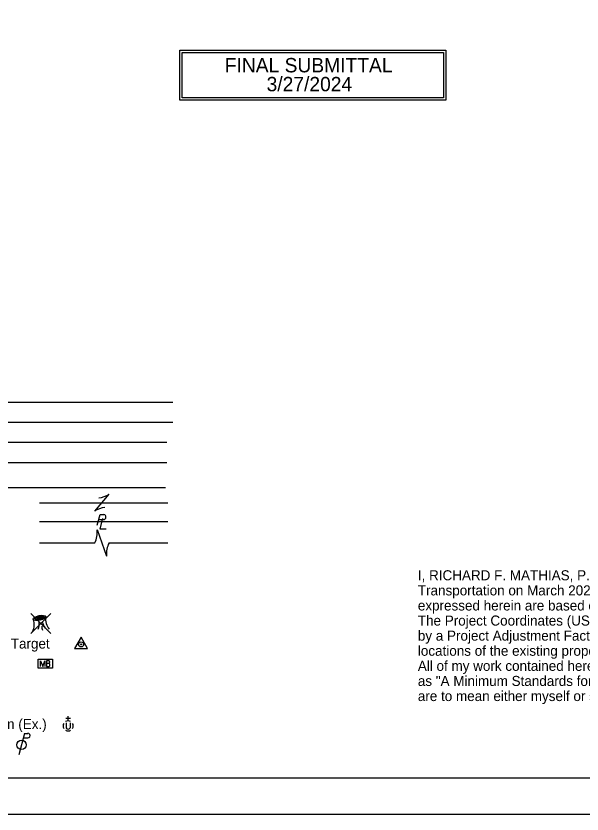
# Model space of a CAD drawing. Extents: x -8.8 to 41.4, y 0 to 34.6.
# Drawn here: x 11.94 to 19.81, y 0 to 11.1 of the extents above; entities that cross this region are included whole.
import ezdxf

# ---------------------------------------------------------------- set-up
doc = ezdxf.new("R2010")
doc.units = 0
for name, color, linetype in [('SH_Cut_Line', 7, 'Continuous'), ('SH_Data', 7, 'Continuous'), ('SH_Text', 7, 'Continuous')]:
    doc.layers.add(name, color=color, linetype=linetype)

msp = doc.modelspace()

# ---------------------------------------------------------------- linework, layer by layer
at = {"layer": 'SH_Cut_Line'}
msp.add_lwpolyline([(1.5, 21.5), (33.5, 21.5), (33.5, 0.5), (1.5, 0.5)], close=True, dxfattribs=at)
at = {"layer": 'SH_Data'}
for p, q in [((10.637, 5.732), (14.12, 5.732)), ((10.637, 5.452), (14.12, 5.452)), ((10.136, 5.172), (14.036, 5.172)), ((10.136, 4.892), (14.036, 4.892)), ((9.668, 4.542), (14.018, 4.542)), ((13.032, 4.212), (13.232, 4.452)), ((12.266, 4.332), (14.049, 4.332)), ((13.132, 4.332), (13.132, 4.332)), ((12.266, 4.068), (14.049, 4.068)), ((13.089, 4.097), (13.154, 4.097)), ((13.13, 4.066), (13.13, 4.066)), ((13.067, 3.957), (13.197, 3.588)), ((12.266, 3.772), (13.032, 3.772)), ((13.132, 3.772), (13.132, 3.772)), ((13.232, 3.772), (14.049, 3.772)), ((12.145, 2.791), (12.423, 2.513)), ((12.423, 2.791), (12.145, 2.513)), ((12.284, 2.652), (12.284, 2.652)), ((12.284, 2.652), (12.284, 2.652)), ((12.345, 2.092), (12.345, 2.092)), ((12.663, 1.296), (12.663, 1.36)), ((12.694, 1.328), (12.631, 1.328)), ((12.635, 1.269), (12.635, 1.2)), ((12.663, 1.226), (12.663, 1.226)), ((12.69, 1.269), (12.69, 1.2)), ((12.058, 1.122), (11.978, 0.822)), ((12.058, 1.122), (12.101, 1.122)), ((12.041, 1.059), (12.101, 1.059))]:
    msp.add_line(p, q, dxfattribs=at)
for points in [[(14.216, 10.629), (17.916, 10.629), (17.916, 9.931), (14.216, 9.931)], [(14.248, 10.597), (17.884, 10.597), (17.884, 9.963), (14.248, 9.963)], [(12.753, 2.302), (12.933, 2.302), (12.843, 2.463)], [(12.245, 2.153), (12.445, 2.153), (12.445, 2.031), (12.245, 2.031)]]:
    msp.add_lwpolyline(points, close=True, dxfattribs=at)
for points in [[(13.068, 4.018), (13.108, 4.166), (13.159, 4.166)], [(13.143, 4.114), (13.103, 3.966), (13.191, 3.966)], [(12.28, 2.052), (12.28, 2.132), (12.309, 2.052), (12.337, 2.132), (12.337, 2.052)], [(12.396, 2.096), (12.399, 2.099), (12.401, 2.101), (12.403, 2.103), (12.403, 2.104), (12.405, 2.107), (12.405, 2.108), (12.406, 2.113), (12.406, 2.115), (12.406, 2.117), (12.406, 2.121), (12.405, 2.124), (12.403, 2.127), (12.399, 2.129), (12.397, 2.131), (12.396, 2.131), (12.393, 2.132), (12.362, 2.132), (12.362, 2.052), (12.396, 2.052), (12.401, 2.055), (12.405, 2.058), (12.408, 2.063), (12.41, 2.069), (12.41, 2.074), (12.41, 2.078), (12.409, 2.082), (12.406, 2.088), (12.403, 2.091), (12.396, 2.096), (12.362, 2.096)]]:
    msp.add_lwpolyline(points, dxfattribs=at)
for centre, radius in [((12.843, 2.36), 0.035), ((12.843, 2.36), 0.008), ((12.016, 0.962), 0.065)]:
    msp.add_circle(centre, radius, dxfattribs=at)
for centre, radius, start, end in [((13.074, 4.667), 0.267, 273.6945, 306.337), ((13.19, 3.997), 0.267, 93.6945, 126.337), ((13.154, 4.132), 0.0345, 270.471, 81.3281), ((12.735, 3.924), 0.334, 332.9422, 5.5848), ((13.529, 3.621), 0.334, 152.9422, 185.5848), ((11.992, 2.635), 0.2, 331.5338, 20.9269), ((12.008, 2.654), 0.253, 340.7938, 3.5481), ((12.609, 2.755), 0.316, 194.9653, 212.1216), ((12.564, 2.709), 0.215, 171.4106, 219.9194), ((12.479, 2.612), 0.182, 178.7926, 197.1224), ((12.663, 1.226), 0.07, 150.0184, 209.9816), ((12.663, 1.226), 0.07, 60.0184, 120.0157), ((12.663, 1.226), 0.07, 330.0184, 29.9816), ((12.102, 1.091), 0.0319, 268.8767, 91.1233), ((12.663, 1.226), 0.07, 239.9843, 299.9816), ((12.663, 1.213), 0.03, 205.1924, 334.8076)]:
    msp.add_arc(centre, radius, start, end, dxfattribs=at)
for major_axis in [(0.0868, 0.0187), (0.0651, 0.0141), (0.0488, 0.0105), (0.0275, 0.0059), (0.0154, 0.0033)]:
    msp.add_ellipse((12.265, 2.728), major_axis=major_axis, ratio=0.36865, dxfattribs=at)
at = {"layer": 'SH_Text'}
msp.add_lwpolyline([(0, 0), (34, 0), (34, 22), (0, 22)], close=True, dxfattribs=at)

# ---------------------------------------------------------------- texts
at = {"layer": 'SH_Data'}
for s, height, p in [('FINAL SUBMITTAL', 0.2, (14.842, 10.319)), ('3/27/2024', 0.2, (15.424, 10.056)), ('I, RICHARD F. MATHIAS, P. S. have conducted a survey of the existing conditions for the Ohio Department of', 0.14, (17.528, 3.252)), ('Transportation on March 2024.  The results of that survey are contained herein.  The horizontal coordinates', 0.14, (17.528, 3.042)), ('expressed herein are based on the Ohio State Plane Coordinate System, South Zone on NAD 83 2011 datum.', 0.14, (17.528, 2.832)), ('The Project Coordinates (US Survey feet) are relative to State Plane Grid Coordinates (meters or US Survey feet)', 0.14, (17.528, 2.622)), ('by a Project Adjustment Factor multiplier of 1.00000000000.  As a part of this project I have reestablished the', 0.14, (17.528, 2.412)), ('Wetland (Pr)         , Grass (Pr)            , Aerial Target    ', 0.14, (8.12, 2.302)), ('locations of the existing property lines and centerline of existing Right of Way for property takes contained herein.  ', 0.14, (17.528, 2.202)), ('All of my work contained herein was conducted in accordance with Ohio Administrative Code 4733-37 commonly known', 0.14, (17.528, 1.992)), ('as "A Minimum Standards for Boundary Surveys in the State of Ohio" unless noted.  The words I and my as used herein', 0.14, (17.528, 1.782)), ('are to mean either myself or someone working under my direct supervision.', 0.14, (17.528, 1.572)), ('Water Valve (Ex)         , Utility Valve Unknown (Ex.)', 0.14, (8.12, 1.182))]:
    msp.add_text(s, height=height, dxfattribs=at).set_placement(p)

doc.saveas('drawing.dxf')
